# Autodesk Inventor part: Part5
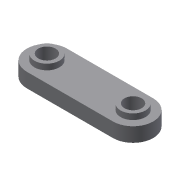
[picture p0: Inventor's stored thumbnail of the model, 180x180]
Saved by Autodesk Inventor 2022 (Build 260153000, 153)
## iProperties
Created: 2002-01
Part Number: Part5
Document SubType Name: Modeling
Designer: ***
Density: 1 g/cm^3
Material: Generic
Appearance: Default
Control State: 0
Master: False
Checked Out: False
Shininess: 77.0
Length Units: 11269
Angle Units: 11279
Time Units: 11290
Mass Units: 11283
Length Display Precision: 3
Angle Display Precision: 2
Density: 0.0
Volumn: 0.0
Area: 0.0
PropertySet Name: Model Information
Author: ***
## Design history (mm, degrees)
sketch "Sketch1"
  geometry: L1 (-33.118, 12.346)-(26.882, 12.361); L2 (-33.111, -15.654)-(26.889, -15.639); C1 r 6 at (-33.114, -1.654); C2 r 6 at (26.886, -1.639); A1 r 14 centre (-33.114, -1.654) between (-33.118, 12.346) and (-33.111, -15.654); A2 r 14 centre (26.886, -1.639) between (26.889, -15.639) and (26.882, 12.361)
  constraints: 4 centre point, 4 end point, 4 point on circle, 4 tangent, 2 coincident, 2 equal radius
  dimensions: "d0" = 60 distance of L1.start L1.end; "d1" = 14 radius of A1; "d2" = 12 diameter of C1
extrude "Extrusion1" new body sketch "Sketch1" distance "d3" = 10; taper "d4" = 0 deg
sketch "Sketch2"
  geometry: C1 r 6 at (26.886, -1.639) reference; C2 r 6 at (-33.114, -1.654) reference; C3 r 8.694 at (-33.114, -1.654); C4 r 8.694 at (26.886, -1.639)
  constraints: 2 centre point, 2 coincident, 1 equal radius
extrude "Extrusion2" join sketch "Sketch2" distance "d5" = 4; taper "d6" = 0 deg
body "Solid1"
